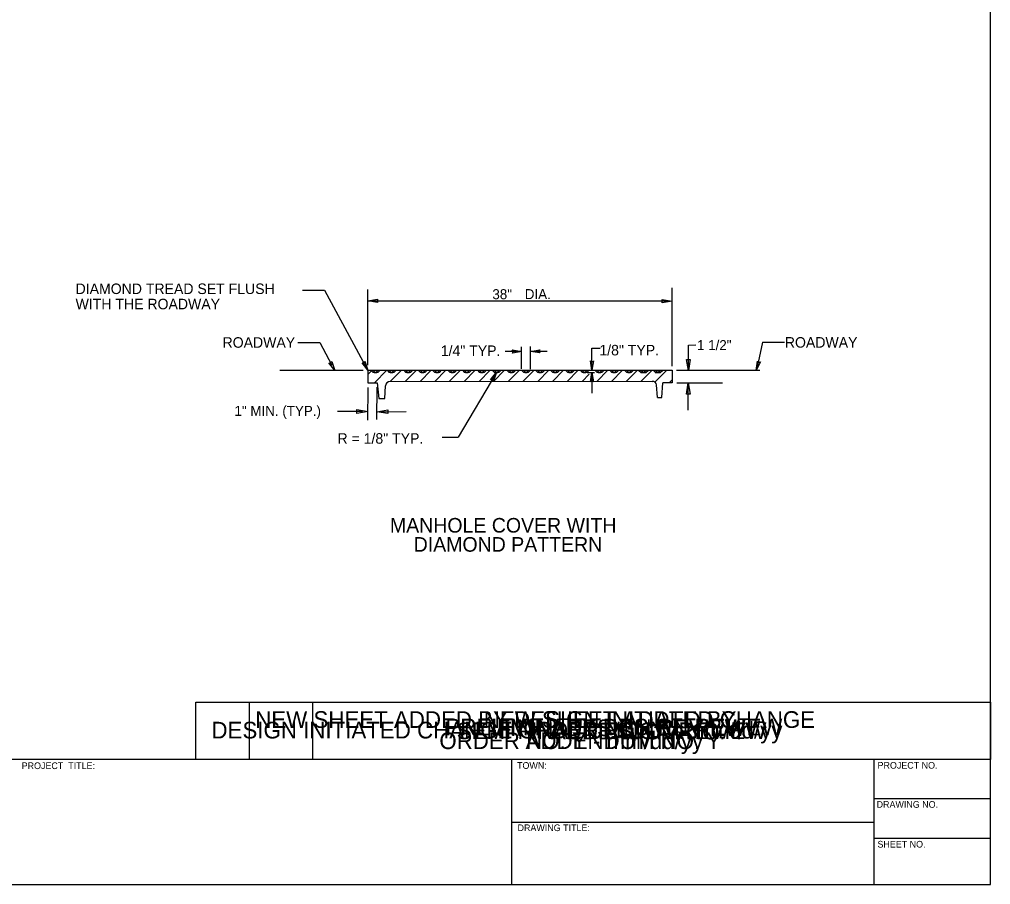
# Model space of a CAD drawing. Extents: x 0 to 31.8, y -0.5 to 20.8.
# Drawn here: x 20.1 to 31.75, y 0 to 10.38 of the extents above; entities that cross this region are included whole.
import ezdxf

# ---------------------------------------------------------------- set-up
doc = ezdxf.new("R2010")
doc.units = 0
for name, color, linetype in [('CT_Border_Perimeter_Shape', 7, 'Continuous'), ('CT_CSHT_GeneralLabel', 7, 'Continuous'), ('CT_Dimensions', 7, 'Continuous'), ('CT_Note_Addendum', 7, 'Continuous'), ('CT_Note_Design_Initiated_Change_Order', 7, 'Continuous'), ('CT_Note_Final_Design_Review', 7, 'Continuous'), ('CT_Note_New_Sheet_by_Addendum', 7, 'Continuous'), ('CT_Note_New_Sheet_by_Design_Initiated_Change_Order', 7, 'Continuous'), ('CT_Note_Preliminary_Design_Review', 7, 'Continuous'), ('CT_Note_Semi_Final_Design_Review', 7, 'Continuous'), ('CT_Title_Block_Linework', 7, 'Continuous'), ('CT_Title_Block_Text', 7, 'Continuous'), ('sb_Dimension Lines', 7, 'Continuous'), ('sb_Existing Structural Steel', 7, 'Continuous')]:
    doc.layers.add(name, color=color, linetype=linetype)

# ---------------------------------------------------------------- blocks, each defined once
blk = doc.blocks.new('Dimension Terminator')
at = {"layer": 'sb_Dimension Lines'}
blk.add_lwpolyline([(-0.119, 0.02), (0, 0), (-0.119, -0.02)], close=True, dxfattribs=at)

msp = doc.modelspace()

# ---------------------------------------------------------------- linework, layer by layer
at = {"layer": 'CT_Border_Perimeter_Shape'}
msp.add_lwpolyline([(0, 0), (31.75, 0), (31.75, 20.75), (0, 20.75)], close=True, dxfattribs=at)
at = {"layer": 'CT_Dimensions'}
for p, q in [((23.496, 7.13), (23.76, 7.13)), ((23.76, 7.13), (24.276, 6.173)), ((24.278, 6.227), (24.278, 7.137)), ((27.929, 6.217), (27.929, 7.156)), ((24.28, 6.999), (27.908, 6.999)), ((24.395, 7.019), (24.395, 6.979)), ((23.439, 6.499), (23.703, 6.499)), ((23.703, 6.499), (23.849, 6.229)), ((26.012, 6.411), (26.125, 6.394)), ((26.124, 6.184), (26.124, 6.448)), ((26.232, 6.179), (26.232, 6.452)), ((26.232, 6.393), (26.344, 6.412)), ((26.966, 6.167), (26.966, 6.434)), ((26.966, 6.434), (27.068, 6.434)), ((28.125, 6.47), (28.213, 6.471)), ((28.125, 6.166), (28.125, 6.47)), ((29.014, 6.504), (28.948, 6.204)), ((29.014, 6.504), (29.278, 6.504)), ((26.124, 6.394), (25.927, 6.394)), ((26.125, 6.394), (26.013, 6.373)), ((26.429, 6.393), (26.232, 6.393)), ((26.344, 6.375), (26.232, 6.393)), ((23.882, 6.165), (23.813, 6.255)), ((23.846, 6.273), (23.882, 6.165)), ((24.278, 6.168), (24.209, 6.258)), ((24.242, 6.276), (24.278, 6.168)), ((26.966, 6.167), (26.95, 6.28)), ((26.988, 6.279), (26.966, 6.167)), ((28.936, 6.166), (28.953, 6.278)), ((28.988, 6.267), (28.936, 6.166)), ((23.225, 6.168), (24.223, 6.168)), ((25.821, 6.142), (25.364, 5.365)), ((25.752, 6.053), (25.822, 6.144)), ((25.822, 6.144), (25.785, 6.036)), ((26.95, 6.028), (26.967, 6.141)), ((26.967, 6.141), (26.966, 5.895)), ((26.967, 6.141), (26.987, 6.029)), ((27.982, 6.167), (28.982, 6.167)), ((24.28, 5.571), (24.281, 5.963)), ((24.388, 5.577), (24.39, 5.964)), ((27.987, 6.016), (28.534, 6.016)), ((28.124, 5.688), (28.124, 5.978)), ((24.213, 5.673), (23.915, 5.673)), ((24.397, 5.67), (24.738, 5.673)), ((25.172, 5.365), (25.364, 5.365))]:
    msp.add_line(p, q, dxfattribs=at)
for centre, start, end in [((25.995, 6.392), 313.9446, 48.0093), ((26.361, 6.394), 133.042, 227.1067), ((23.821, 6.279), 250.8867, 344.9514), ((24.218, 6.283), 250.8867, 344.9514), ((26.969, 6.296), 221.5049, 315.5695), ((28.976, 6.289), 204.9353, 299), ((25.76, 6.029), 14.7642, 108.8289), ((26.968, 6.011), 43.6938, 137.7585)]:
    msp.add_arc(centre, 0.0256, start, end, dxfattribs=at)
at = {"layer": 'CT_Note_Addendum'}
msp.add_lwpolyline([(23.621, 2.186), (31.75, 2.186), (31.75, 1.5), (23.621, 1.5)], close=True, dxfattribs=at)
msp.add_lwpolyline([(23.621, 2.186), (31.75, 2.186), (31.75, 1.5), (23.621, 1.5)], close=True, dxfattribs=at)
at = {"layer": 'CT_Note_Design_Initiated_Change_Order'}
msp.add_lwpolyline([(22.217, 2.186), (31.75, 2.186), (31.75, 1.5), (22.217, 1.5)], close=True, dxfattribs=at)
msp.add_lwpolyline([(22.217, 2.186), (31.75, 2.186), (31.75, 1.5), (22.217, 1.5)], close=True, dxfattribs=at)
at = {"layer": 'CT_Note_Final_Design_Review'}
msp.add_lwpolyline([(23.621, 2.186), (31.75, 2.186), (31.75, 1.5), (23.621, 1.5)], close=True, dxfattribs=at)
at = {"layer": 'CT_Note_New_Sheet_by_Addendum'}
msp.add_lwpolyline([(23.621, 2.186), (31.75, 2.186), (31.75, 1.5), (23.621, 1.5)], close=True, dxfattribs=at)
msp.add_lwpolyline([(23.621, 2.186), (31.75, 2.186), (31.75, 1.5), (23.621, 1.5)], close=True, dxfattribs=at)
at = {"layer": 'CT_Note_New_Sheet_by_Design_Initiated_Change_Order'}
msp.add_lwpolyline([(22.858, 2.186), (31.75, 2.186), (31.75, 1.5), (22.858, 1.5)], close=True, dxfattribs=at)
msp.add_lwpolyline([(22.858, 2.186), (31.75, 2.186), (31.75, 1.5), (22.858, 1.5)], close=True, dxfattribs=at)
at = {"layer": 'CT_Note_Preliminary_Design_Review'}
msp.add_lwpolyline([(23.621, 2.186), (31.75, 2.186), (31.75, 1.5), (23.621, 1.5)], close=True, dxfattribs=at)
at = {"layer": 'CT_Note_Semi_Final_Design_Review'}
msp.add_lwpolyline([(23.621, 2.186), (31.75, 2.186), (31.75, 1.5), (23.621, 1.5)], close=True, dxfattribs=at)
msp.add_lwpolyline([(23.621, 2.186), (31.75, 2.186), (31.75, 1.5), (23.621, 1.5)], close=True, dxfattribs=at)
at = {"layer": 'CT_Title_Block_Linework'}
for p, q in [((31.75, 1.5), (0, 1.5)), ((26.004, 1.5), (26.004, 0)), ((30.351, 1.5), (30.351, 0)), ((30.351, 1.031), (31.75, 1.031)), ((26.004, 0.75), (30.351, 0.75)), ((30.351, 0.556), (31.75, 0.556))]:
    msp.add_line(p, q, dxfattribs=at)
at = {"layer": 'sb_Existing Structural Steel'}
for p, q in [((24.278, 6.168), (27.93, 6.167)), ((24.278, 6.168), (24.279, 6.015)), ((24.279, 6.117), (24.329, 6.168)), ((24.316, 6.168), (24.339, 6.145)), ((24.339, 6.145), (24.37, 6.168)), ((24.359, 6.016), (24.506, 6.168)), ((24.37, 6.168), (24.402, 6.145)), ((24.402, 6.145), (24.425, 6.168)), ((24.509, 6.167), (24.532, 6.145)), ((24.532, 6.145), (24.563, 6.167)), ((24.551, 6.035), (24.683, 6.168)), ((24.563, 6.167), (24.595, 6.144)), ((24.595, 6.144), (24.618, 6.167)), ((24.709, 6.168), (24.732, 6.145)), ((24.732, 6.036), (24.864, 6.168)), ((24.732, 6.145), (24.764, 6.168)), ((24.764, 6.168), (24.795, 6.145)), ((24.795, 6.145), (24.819, 6.168)), ((24.883, 6.168), (24.905, 6.145)), ((24.905, 6.145), (24.937, 6.168)), ((24.906, 6.034), (25.038, 6.167)), ((24.937, 6.168), (24.968, 6.145)), ((24.968, 6.145), (24.992, 6.168)), ((25.055, 6.167), (25.078, 6.144)), ((25.078, 6.144), (25.109, 6.167)), ((25.082, 6.034), (25.214, 6.167)), ((25.109, 6.167), (25.141, 6.144)), ((25.141, 6.144), (25.164, 6.167)), ((25.238, 6.167), (25.261, 6.144)), ((25.26, 6.035), (25.392, 6.168)), ((25.261, 6.144), (25.293, 6.167)), ((25.293, 6.167), (25.324, 6.144)), ((25.324, 6.144), (25.348, 6.167)), ((25.413, 6.167), (25.436, 6.145)), ((25.435, 6.034), (25.568, 6.167)), ((25.436, 6.145), (25.468, 6.167)), ((25.468, 6.167), (25.499, 6.144)), ((25.499, 6.144), (25.523, 6.167)), ((25.593, 6.168), (25.616, 6.145)), ((25.613, 6.034), (25.746, 6.167)), ((25.616, 6.145), (25.647, 6.167)), ((25.647, 6.167), (25.679, 6.145)), ((25.679, 6.145), (25.702, 6.167)), ((25.77, 6.168), (25.793, 6.145)), ((25.788, 6.034), (25.92, 6.167)), ((25.793, 6.145), (25.825, 6.167)), ((25.825, 6.167), (25.856, 6.145)), ((25.856, 6.145), (25.88, 6.167)), ((25.947, 6.167), (25.969, 6.144)), ((25.968, 6.035), (26.099, 6.167)), ((25.969, 6.144), (26.001, 6.167)), ((26.001, 6.167), (26.032, 6.144)), ((26.032, 6.144), (26.056, 6.167)), ((26.123, 6.167), (26.145, 6.145)), ((26.143, 6.035), (26.276, 6.168)), ((26.145, 6.145), (26.177, 6.167)), ((26.177, 6.167), (26.208, 6.144)), ((26.208, 6.144), (26.232, 6.167)), ((26.292, 6.167), (26.315, 6.144)), ((26.315, 6.144), (26.346, 6.167)), ((26.319, 6.034), (26.451, 6.167)), ((26.346, 6.167), (26.378, 6.144)), ((26.378, 6.144), (26.401, 6.167)), ((26.472, 6.167), (26.495, 6.145)), ((26.495, 6.145), (26.527, 6.167)), ((26.496, 6.034), (26.628, 6.167)), ((26.527, 6.167), (26.558, 6.145)), ((26.558, 6.145), (26.582, 6.167)), ((26.65, 6.167), (26.673, 6.144)), ((26.671, 6.034), (26.804, 6.167)), ((26.673, 6.144), (26.705, 6.167)), ((26.705, 6.167), (26.736, 6.144)), ((26.736, 6.144), (26.76, 6.167)), ((26.826, 6.167), (26.849, 6.144)), ((26.849, 6.144), (26.88, 6.167)), ((26.849, 6.034), (26.936, 6.121)), ((26.88, 6.167), (26.912, 6.144)), ((26.909, 6.141), (26.997, 6.141)), ((26.912, 6.144), (26.935, 6.167)), ((27.003, 6.167), (27.026, 6.144)), ((27.025, 6.034), (27.158, 6.167)), ((27.026, 6.144), (27.058, 6.167)), ((27.058, 6.167), (27.089, 6.144)), ((27.089, 6.144), (27.113, 6.167)), ((27.181, 6.167), (27.204, 6.144)), ((27.203, 6.034), (27.335, 6.167)), ((27.204, 6.144), (27.236, 6.167)), ((27.236, 6.167), (27.267, 6.144)), ((27.267, 6.144), (27.291, 6.167)), ((27.359, 6.167), (27.381, 6.144)), ((27.379, 6.033), (27.511, 6.166)), ((27.381, 6.144), (27.413, 6.167)), ((27.413, 6.167), (27.444, 6.144)), ((27.444, 6.144), (27.468, 6.167)), ((27.532, 6.166), (27.555, 6.144)), ((27.555, 6.144), (27.586, 6.166)), ((27.557, 6.035), (27.688, 6.166)), ((27.586, 6.166), (27.618, 6.143)), ((27.618, 6.143), (27.641, 6.166)), ((27.706, 6.166), (27.728, 6.143)), ((27.722, 6.025), (27.864, 6.166)), ((27.728, 6.143), (27.76, 6.166)), ((27.76, 6.166), (27.791, 6.143)), ((27.791, 6.143), (27.815, 6.166)), ((27.93, 6.167), (27.929, 6.016)), ((24.279, 6.015), (24.392, 6.016)), ((24.392, 6.016), (24.409, 5.831)), ((24.481, 5.831), (24.492, 5.982)), ((24.546, 6.035), (27.692, 6.034)), ((27.755, 5.843), (27.744, 5.993)), ((27.805, 5.843), (27.819, 6.016)), ((27.929, 6.016), (27.819, 6.016)), ((27.893, 6.016), (27.929, 6.052)), ((24.409, 5.831), (24.481, 5.831)), ((27.755, 5.843), (27.805, 5.843))]:
    msp.add_line(p, q, dxfattribs=at)
for centre, radius, start, end in [((24.371, 6.274), 0.133, 256.1046, 283.5488), ((24.564, 6.273), 0.133, 256.1046, 283.5488), ((24.764, 6.274), 0.133, 256.1046, 283.5488), ((24.937, 6.274), 0.133, 256.1046, 283.5488), ((25.11, 6.273), 0.133, 256.1046, 283.5488), ((25.293, 6.273), 0.133, 256.1046, 283.5488), ((25.468, 6.273), 0.133, 256.1046, 283.5488), ((25.647, 6.274), 0.133, 256.1046, 283.5488), ((25.825, 6.274), 0.133, 256.1046, 283.5488), ((26.001, 6.273), 0.133, 256.1046, 283.5488), ((26.177, 6.273), 0.133, 256.1046, 283.5488), ((26.347, 6.273), 0.133, 256.1046, 283.5488), ((26.527, 6.274), 0.133, 256.1046, 283.5488), ((26.705, 6.273), 0.133, 256.1046, 283.5488), ((26.88, 6.273), 0.133, 256.1046, 283.5488), ((27.058, 6.273), 0.133, 256.1046, 283.5488), ((27.236, 6.273), 0.133, 256.1046, 283.5488), ((27.413, 6.273), 0.133, 256.1046, 283.5488), ((27.587, 6.272), 0.133, 256.1046, 283.5488), ((27.76, 6.272), 0.133, 256.1046, 283.5488), ((24.547, 5.979), 0.0555, 91.6232, 176.8554), ((27.694, 5.984), 0.0504, 9.9769, 92.7519)]:
    msp.add_arc(centre, radius, start, end, dxfattribs=at)

# ---------------------------------------------------------------- block references
at = {"layer": 'CT_Dimensions'}
for p, xscale, yscale, rotation in [((24.278, 6.999), 0.9982882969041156, 0.9982552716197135, 180), ((28.125, 6.165), 1.1197916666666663, 1.1197916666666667, -90.19425815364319), ((28.123, 6.016), 1.1197916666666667, 1.1197916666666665, 90.29818676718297), ((24.281, 5.673), 1.1197916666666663, 1.1197916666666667, -0.19425815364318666), ((24.387, 5.671), 1.1197916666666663, 1.1197916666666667, 179.80574184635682)]:
    msp.add_blockref('Dimension Terminator', p, dxfattribs=dict(at, xscale=xscale, yscale=yscale, rotation=rotation))
at = {"layer": 'CT_Dimensions', "xscale": 0.9982882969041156, "yscale": 0.9982552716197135}
msp.add_blockref('Dimension Terminator', (27.93, 6.998), dxfattribs=at)

# ---------------------------------------------------------------- texts
at = {"layer": 'CT_CSHT_GeneralLabel'}
for s, p in [('MANHOLE COVER WITH', (24.544, 4.221)), ('DIAMOND PATTERN', (24.829, 3.992))]:
    msp.add_text(s, height=0.175, dxfattribs=at).set_placement(p)
at = {"layer": 'CT_Dimensions'}
for s, height, p in [('DIAMOND TREAD SET FLUSH', 0.1261, (20.773, 7.082)), ('38" ', 0.12, (25.773, 7.02)), ('DIA.', 0.12, (26.162, 7.021)), ('WITH THE ROADWAY', 0.1261, (20.773, 6.899)), ('ROADWAY', 0.1261, (22.536, 6.438)), ('1 1/2" ', 0.12, (28.228, 6.409)), ('ROADWAY', 0.1261, (29.282, 6.439)), ('1/4" TYP.', 0.1261, (25.154, 6.339)), ('1/8" TYP.', 0.1261, (27.057, 6.346)), ('1" MIN. (TYP.)', 0.12, (22.679, 5.621)), ('R = 1/8" TYP.', 0.1261, (23.915, 5.287))]:
    msp.add_text(s, height=height, dxfattribs=at).set_placement(p)
at = {"layer": 'CT_Note_Addendum'}
msp.add_text('ADDENDUM NO. Y', height=0.2, dxfattribs=at).set_placement((26.475, 1.741))
at = {"layer": 'CT_Note_Design_Initiated_Change_Order'}
msp.add_text('DESIGN INITIATED CHANGE ORDER NO. Y - mm/dd/yy', height=0.2, dxfattribs=at).set_placement((22.403, 1.752))
at = {"layer": 'CT_Note_Final_Design_Review'}
msp.add_text('FINAL DESIGN REVIEW', height=0.2, dxfattribs=at).set_placement((25.825, 1.78))
at = {"layer": 'CT_Note_New_Sheet_by_Addendum'}
for s, p in [('NEW SHEET ADDED BY', (25.67, 1.879)), ('ADDENDUM NO. Y', (26.171, 1.625))]:
    msp.add_text(s, height=0.2, dxfattribs=at).set_placement(p)
at = {"layer": 'CT_Note_New_Sheet_by_Design_Initiated_Change_Order'}
for s, p in [('NEW SHEET ADDED BY DESIGN INITIATED CHANGE', (22.928, 1.879)), ('ORDER NO. Y - mm/dd/yy', (25.137, 1.625))]:
    msp.add_text(s, height=0.2, dxfattribs=at).set_placement(p)
at = {"layer": 'CT_Note_Preliminary_Design_Review'}
msp.add_text('PRELIMINARY DESIGN REVIEW', height=0.2, rotation=360, dxfattribs=at).set_placement((25.21, 1.789))
at = {"layer": 'CT_Note_Semi_Final_Design_Review'}
msp.add_text('SEMI FINAL DESIGN REVIEW', height=0.2, dxfattribs=at).set_placement((25.346, 1.744))
at = {"layer": 'CT_Title_Block_Text'}
for s, p in [('PROJECT  TITLE:', (20.126, 1.385)), ('TOWN:', (26.069, 1.388)), ('PROJECT NO.', (30.394, 1.39)), ('DRAWING NO.', (30.383, 0.921)), ('DRAWING TITLE:', (26.075, 0.641)), ('SHEET NO.', (30.393, 0.444))]:
    msp.add_text(s, height=0.08, rotation=360, dxfattribs=at).set_placement(p)

doc.saveas('drawing.dxf')
